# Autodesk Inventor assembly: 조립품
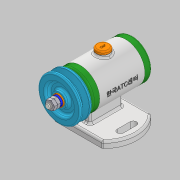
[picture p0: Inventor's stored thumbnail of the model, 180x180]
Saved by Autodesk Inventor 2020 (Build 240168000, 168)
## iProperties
Created: 2021-09
Part Number: 조립품
Document SubType Name: Assembly
Designer: Administrator
Author: Administrator
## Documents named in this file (14)
- C:\Users\Administrator\Desktop\710906V1012\조립품.iam
- C:\Users\Administrator\Desktop\710906V1012\본체.ipt
- C:\Users\Administrator\Desktop\710906V1012\V벨트풀리.ipt
- C:\Users\Administrator\Desktop\710906V1012\너트 M8.ipt
- C:\Users\Administrator\Desktop\710906V1012\뒤커버.ipt
- C:\Users\Administrator\Desktop\710906V1012\베어링 15x32x9.ipt
- C:\Users\Administrator\Desktop\710906V1012\볼트 M4x12.ipt
- C:\Users\Administrator\Desktop\710906V1012\스프링와셔 8.ipt
- C:\Users\Administrator\Desktop\710906V1012\앞커버.ipt
- C:\Users\Administrator\Desktop\710906V1012\오일 실 15x25x7.ipt
- C:\Users\Administrator\Desktop\710906V1012\와셔 8x17.ipt
- C:\Users\Administrator\Desktop\710906V1012\축.ipt
- C:\Users\Administrator\Desktop\710906V1012\캡.ipt
- C:\Users\Administrator\Desktop\710906V1012\키 3x3.ipt
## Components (1 placed, 1 different names)
1. V벨트풀리:1
